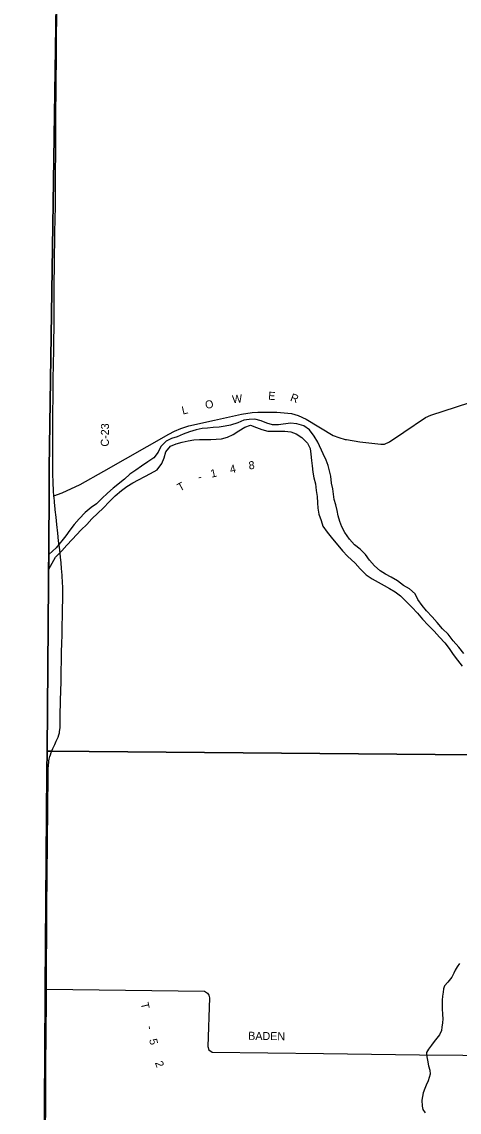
# Model space of a CAD drawing. Extents: x 1312308 to 1684953, y 460642 to 865172.
# Drawn here: x 1410763 to 1414861, y 606234 to 616453 of the extents above; entities that cross this region are included whole.
import ezdxf

# ---------------------------------------------------------------- set-up
doc = ezdxf.new("R2010")
doc.units = 0
for name, color, linetype in [('GM_X_Adjacent_County', 7, 'Continuous'), ('GM_X_County', 7, 'Continuous'), ('GM_X_County_Road', 7, 'Continuous'), ('GM_X_County_Road_Text', 7, 'Continuous'), ('GM_X_Major_River', 7, 'Continuous'), ('GM_X_Minor_River', 7, 'Continuous'), ('GM_X_Township', 7, 'Continuous'), ('GM_X_Township_Road', 7, 'Continuous'), ('GM_X_Township_Road_Text', 7, 'Continuous')]:
    doc.layers.add(name, color=color, linetype=linetype)

msp = doc.modelspace()

# ---------------------------------------------------------------- linework, layer by layer
at = {"layer": 'GM_X_Adjacent_County'}
msp.add_lwpolyline([(1411211, 633565), (1411180, 628296), (1411163, 625648), (1411153, 624951), (1411095, 617624), (1411090, 617033), (1411020, 612269), (1411018, 611981), (1410999, 609618), (1410998, 609429), (1410982, 607392), (1410977, 606751), (1410955, 603992), (1410939, 601893), (1410907, 597962), (1410895, 596474), (1410841, 590631), (1410839, 590333), (1410790, 585032), (1410763, 583224)], dxfattribs=at)
at = {"layer": 'GM_X_County'}
msp.add_lwpolyline([(1410955, 603992), (1410977, 606751), (1410982, 607392), (1410998, 609429), (1410999, 609618), (1411018, 611981), (1411020, 612269), (1411090, 617033), (1411095, 617624), (1411153, 624951), (1411163, 625648), (1411180, 628296), (1411211, 633565)], dxfattribs=at)
at = {"layer": 'GM_X_County_Road'}
for points in [[(1411053, 612576), (1411053, 612621), (1411053, 612699), (1411054, 612802), (1411056, 612925), (1411058, 613103), (1411062, 613379), (1411063, 613427), (1411065, 613630), (1411067, 613849), (1411067, 613919), (1411067, 613984), (1411070, 614182), (1411073, 614476), (1411075, 614606), (1411077, 614720), (1411077, 614867), (1411078, 614990), (1411081, 615271), (1411083, 615557), (1411086, 615852), (1411087, 616151), (1411092, 616667)], [(1411052, 612418), (1411053, 612528), (1411053, 612576)], [(1411070, 611943), (1411068, 611965), (1411066, 611990), (1411064, 612012), (1411063, 612018), (1411061, 612049), (1411059, 612080), (1411057, 612114), (1411055, 612154), (1411054, 612199), (1411053, 612270), (1411052, 612412), (1411052, 612418)], [(1411015, 609509), (1411017, 609526), (1411020, 609544), (1411025, 609567), (1411030, 609584), (1411037, 609604), (1411043, 609618), (1411044, 609621), (1411054, 609644), (1411071, 609679), (1411086, 609711), (1411102, 609748), (1411110, 609771), (1411115, 609789), (1411117, 609802), (1411119, 609819), (1411121, 609840), (1411121, 609859), (1411122, 609890), (1411123, 609944), (1411126, 610091), (1411130, 610269), (1411132, 610371), (1411134, 610465), (1411136, 610546), (1411138, 610630), (1411140, 610705), (1411141, 610791), (1411143, 610885), (1411144, 610965), (1411146, 611030), (1411147, 611106), (1411146, 611163), (1411145, 611190), (1411144, 611217), (1411142, 611243), (1411141, 611268), (1411136, 611330), (1411131, 611381), (1411125, 611435), (1411118, 611505), (1411108, 611590), (1411100, 611662), (1411091, 611743), (1411084, 611812), (1411076, 611880), (1411072, 611927), (1411070, 611943)], [(1410984, 606093), (1410987, 606272), (1410987, 606402), (1410988, 606584), (1410989, 606747), (1410990, 606894), (1410991, 606992), (1410992, 607094), (1410993, 607155), (1410994, 607299), (1410994, 607386), (1410994, 607390), (1410994, 607442), (1410994, 607558), (1410995, 607614), (1410995, 607706), (1410996, 607822), (1410997, 607883), (1410997, 607939), (1410997, 608033), (1410998, 608165), (1411000, 608435), (1411003, 608781), (1411006, 609065), (1411007, 609166), (1411009, 609309), (1411010, 609403), (1411011, 609429), (1411011, 609460), (1411012, 609478), (1411013, 609492), (1411015, 609509)]]:
    msp.add_lwpolyline(points, dxfattribs=at)
at = {"layer": 'GM_X_Major_River'}
msp.add_line((1411017, 611461), (1411016, 611324), dxfattribs=at)
for points in [[(1414904, 610534), (1414857, 610591), (1414804, 610653), (1414758, 610714), (1414706, 610765), (1414654, 610822), (1414609, 610875), (1414556, 610932), (1414515, 610983), (1414474, 611038), (1414449, 611091), (1414397, 611138), (1414338, 611170), (1414283, 611215), (1414223, 611248), (1414172, 611275), (1414120, 611308), (1414067, 611356), (1414022, 611407), (1413983, 611462), (1413932, 611511), (1413879, 611550), (1413834, 611603), (1413789, 611666), (1413762, 611719), (1413743, 611769), (1413726, 611822), (1413717, 611874), (1413704, 611925), (1413691, 611977), (1413682, 612027), (1413677, 612077), (1413666, 612130), (1413657, 612194), (1413646, 612244), (1413633, 612295), (1413616, 612345), (1413588, 612404), (1413538, 612513), (1413503, 612570), (1413458, 612629), (1413405, 612668), (1413339, 612686), (1413281, 612693), (1413168, 612676), (1413112, 612677), (1413058, 612690), (1413005, 612713), (1412947, 612730), (1412893, 612726), (1412842, 612719), (1412786, 612696), (1412717, 612673), (1412667, 612662), (1412612, 612653), (1412556, 612651), (1412504, 612646), (1412452, 612641), (1412395, 612630), (1412335, 612609), (1412276, 612587), (1412220, 612564), (1412165, 612547), (1412114, 612524), (1412065, 612473), (1412040, 612421), (1412001, 612368), (1411944, 612329), (1411883, 612288), (1411830, 612252), (1411775, 612213), (1411724, 612168), (1411618, 612082), (1411565, 612035), (1411514, 611984), (1411463, 611937), (1411412, 611902), (1411355, 611853), (1411299, 611796), (1411252, 611743), (1411213, 611688), (1411176, 611636), (1411085, 611522), (1411017, 611461)], [(1411016, 611324), (1411079, 611436), (1411137, 611495), (1411186, 611548), (1411233, 611601), (1411319, 611691), (1411371, 611742), (1411418, 611794), (1411528, 611899), (1411581, 611954), (1411637, 612011), (1411696, 612060), (1411747, 612097), (1411802, 612132), (1411856, 612161), (1411917, 612192), (1411970, 612220), (1412031, 612255), (1412076, 612312), (1412097, 612368), (1412112, 612424), (1412156, 612475), (1412210, 612498), (1412265, 612513), (1412321, 612526), (1412375, 612536), (1412428, 612539), (1412534, 612537), (1412584, 612540), (1412634, 612545), (1412689, 612560), (1412743, 612585), (1412796, 612621), (1412851, 612654), (1412907, 612673), (1412961, 612652), (1413013, 612631), (1413069, 612618), (1413121, 612616), (1413175, 612617), (1413227, 612616), (1413283, 612609), (1413335, 612590), (1413388, 612557), (1413441, 612505), (1413464, 612455), (1413471, 612401), (1413478, 612342), (1413485, 612292), (1413490, 612232), (1413499, 612179), (1413514, 612123), (1413522, 612061), (1413529, 612003), (1413534, 611946), (1413537, 611894), (1413546, 611838), (1413567, 611779), (1413584, 611727), (1413625, 611670), (1413675, 611609), (1413724, 611547), (1413767, 611496), (1413816, 611445), (1413885, 611380), (1413932, 611325), (1413991, 611271), (1414045, 611234), (1414102, 611201), (1414157, 611169), (1414209, 611142), (1414261, 611111), (1414312, 611072), (1414363, 611021), (1414418, 610967), (1414469, 610912), (1414516, 610855), (1414569, 610798), (1414626, 610741), (1414677, 610685), (1414726, 610634), (1414767, 610581), (1414806, 610522), (1414845, 610469), (1414890, 610414)]]:
    msp.add_lwpolyline(points, dxfattribs=at)
at = {"layer": 'GM_X_Minor_River'}
msp.add_lwpolyline([(1414864, 607629), (1414841, 607595), (1414825, 607565), (1414812, 607536), (1414791, 607500), (1414756, 607452), (1414725, 607419), (1414713, 607389), (1414710, 607359), (1414705, 607321), (1414702, 607283), (1414702, 607251), (1414703, 607207), (1414704, 607150), (1414707, 607108), (1414706, 607070), (1414699, 607032), (1414695, 607000), (1414676, 606958), (1414651, 606927), (1414628, 606895), (1414602, 606861), (1414575, 606826), (1414556, 606792), (1414559, 606754), (1414563, 606722), (1414573, 606667), (1414587, 606629), (1414588, 606591), (1414581, 606559), (1414571, 606527), (1414552, 606487), (1414539, 606455), (1414524, 606417), (1414511, 606346), (1414514, 606289), (1414521, 606259), (1414542, 606227)], dxfattribs=at)
at = {"layer": 'GM_X_Township'}
for points in [[(1443487, 629689), (1443383, 625252), (1443279, 619937), (1443263, 619245), (1443164, 614625), (1443063, 609310), (1440472, 609335), (1437771, 609361), (1435200, 609380), (1434197, 609393), (1430058, 609438), (1427248, 609465), (1424759, 609498), (1422201, 609520), (1411036, 609618), (1410999, 609618), (1411018, 611981), (1411020, 612269), (1411090, 617033), (1411095, 617624), (1411153, 624951), (1411163, 625648), (1411180, 628296), (1411211, 633565)], [(1410955, 603992), (1410977, 606751), (1410982, 607392), (1410998, 609429), (1410999, 609618), (1411036, 609618), (1422201, 609520), (1424759, 609498), (1427248, 609465), (1430058, 609438), (1434197, 609393), (1435200, 609380), (1437771, 609361), (1440472, 609335), (1443063, 609310), (1445748, 609283), (1452218, 609195), (1453828, 609169), (1453804, 608987), (1453761, 603814)]]:
    msp.add_lwpolyline(points, dxfattribs=at)
at = {"layer": 'GM_X_Township_Road'}
for points in [[(1413806, 612537), (1413931, 612515), (1414126, 612494), (1414160, 612496), (1414208, 612517), (1414343, 612607), (1414545, 612744), (1414595, 612766), (1415798, 613157)], [(1411064, 612012), (1411141, 612038), (1411310, 612117), (1411530, 612243), (1412139, 612587), (1412193, 612616), (1412254, 612642), (1412329, 612665), (1412568, 612721), (1412820, 612775), (1412922, 612791), (1412973, 612794), (1413152, 612794), (1413289, 612781), (1413351, 612764), (1413426, 612729), (1413680, 612575), (1413732, 612557), (1413794, 612539), (1413806, 612537)], [(1410994, 607386), (1412476, 607368), (1412503, 607351), (1412515, 607332), (1412520, 607305), (1412506, 606850), (1412515, 606820), (1412545, 606797), (1413589, 606785), (1414490, 606772), (1415704, 606761), (1416607, 606753), (1416746, 606747), (1416845, 606735), (1417827, 606600), (1418190, 606549), (1418495, 606508)]]:
    msp.add_lwpolyline(points, dxfattribs=at)

# ---------------------------------------------------------------- texts
at = {"layer": 'GM_X_County_Road_Text'}
msp.add_text('C-23', height=75, rotation=89.6585, dxfattribs=at).set_placement((1411578, 612472))
at = {"layer": 'GM_X_Township_Road_Text'}
for s, rotation, p in [('W', 5.5837, (1412737, 612878)), ('E', 356.4364, (1413070, 612912)), ('R', 339.9579, (1413272, 612903)), ('L', 13.2094, (1412271, 612772)), ('O', 12.4691, (1412489, 612823)), ('8', 4.7881, (1412891, 612258)), ('1', 12.6011, (1412540, 612180)), ('4', 12.303, (1412720, 612220)), ('T', 28.8598, (1412245, 612050)), ('-', 14.0183, (1412423, 612150)), ('T', 283.2463, (1411875, 607254)), ('-', 283.307, (1411926, 607035)), ('5', 283.5826, (1411955, 606913)), ('BADEN', 359.2023, (1412884, 606913)), ('2', 290.0394, (1412009, 606698))]:
    msp.add_text(s, height=75, rotation=rotation, dxfattribs=at).set_placement(p)

doc.saveas('drawing.dxf')
